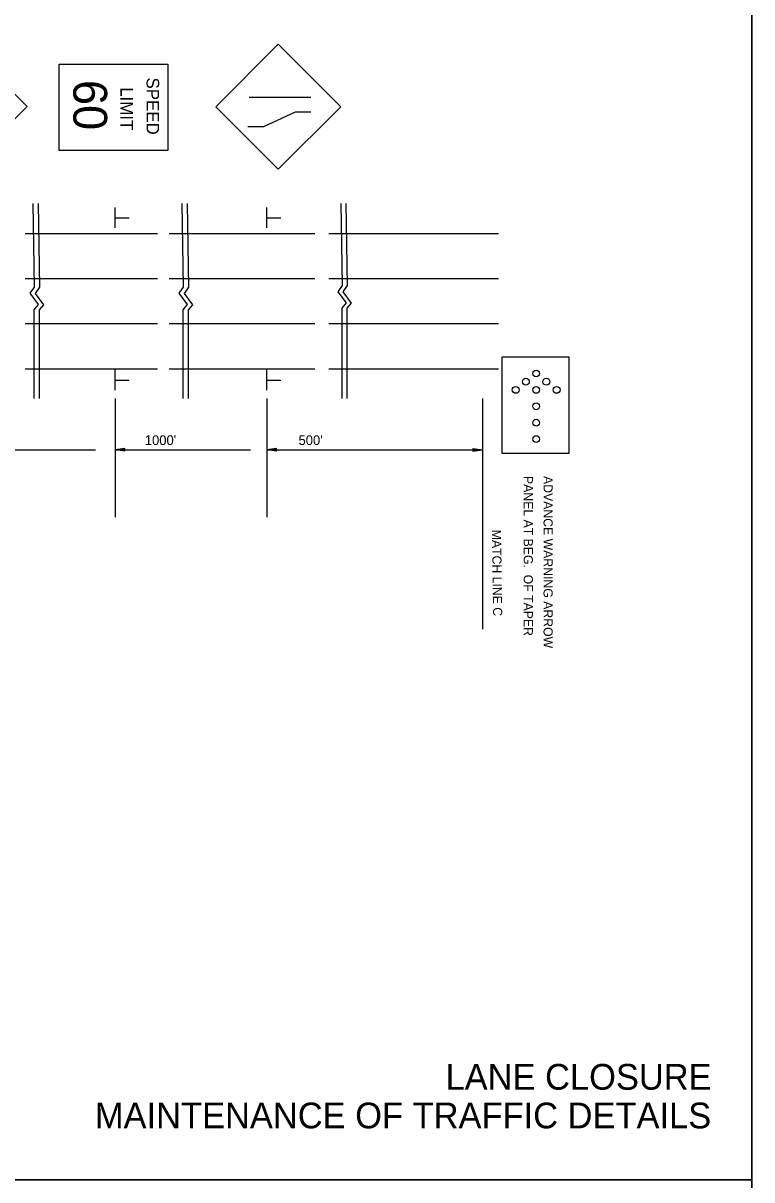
# Model space of a CAD drawing. Extents: x -100 to 745, y -1581 to -107.
# Drawn here: x 295.9 to 345.4, y -810.6 to -732 of the extents above; entities that cross this region are included whole.
import ezdxf

# ---------------------------------------------------------------- set-up
doc = ezdxf.new("R2010")
doc.units = 0
for name, color, linetype in [('Default', 7, 'Continuous'), ('R_Contour Annot', 7, 'Continuous'), ('R_Draft', 7, 'Continuous'), ('R_MOT', 7, 'Continuous')]:
    doc.layers.add(name, color=color, linetype=linetype)

msp = doc.modelspace()

# ---------------------------------------------------------------- linework, layer by layer
at = {"layer": 'Default'}
for p, q in [((291.935, -733.443), (296.177, -737.674)), ((308.988, -737.689), (313.233, -733.444)), ((313.233, -733.444), (317.477, -737.689)), ((311.266, -737.041), (315.442, -737.041)), ((296.177, -737.674), (291.95, -741.919)), ((313.233, -741.933), (308.988, -737.689)), ((317.477, -737.689), (313.233, -741.933)), ((312.257, -739.02), (314.414, -738.03)), ((314.414, -738.03), (315.442, -738.03)), ((311.176, -739.02), (312.257, -739.02)), ((302.151, -745.916), (302.151, -744.538)), ((312.458, -745.916), (312.458, -744.538)), ((302.171, -745.231), (303.112, -745.231)), ((312.478, -745.231), (313.419, -745.231)), ((296.044, -746.294), (305.039, -746.294)), ((305.818, -746.294), (315.713, -746.294)), ((316.663, -746.294), (324.214, -746.294)), ((324.214, -746.294), (328.2, -746.294)), ((296.044, -749.356), (305.039, -749.356)), ((305.818, -749.356), (315.713, -749.356)), ((316.663, -749.356), (324.214, -749.356)), ((324.214, -749.356), (328.2, -749.356)), ((296.044, -752.419), (305.039, -752.419)), ((305.818, -752.419), (315.713, -752.419)), ((316.663, -752.419), (324.214, -752.419)), ((324.214, -752.419), (328.2, -752.419)), ((296.044, -755.481), (305.039, -755.481)), ((302.151, -756.938), (302.151, -755.56)), ((305.818, -755.481), (315.713, -755.481)), ((312.458, -756.938), (312.458, -755.56)), ((316.663, -755.481), (324.214, -755.481)), ((324.214, -755.481), (328.2, -755.481)), ((302.171, -756.252), (303.112, -756.252)), ((312.479, -756.252), (313.419, -756.252)), ((302.151, -757.508), (302.151, -765.561)), ((312.458, -757.508), (312.458, -765.561)), ((327.11, -757.508), (327.11, -773.174)), ((291.636, -760.99), (300.829, -760.99)), ((302.812, -760.891), (302.151, -760.99)), ((302.151, -760.99), (311.344, -760.99)), ((302.812, -761.089), (302.151, -760.99)), ((302.812, -760.907), (302.261, -760.99)), ((302.812, -761.072), (302.261, -760.99)), ((302.812, -760.924), (302.375, -760.99)), ((302.812, -761.056), (302.375, -760.99)), ((302.812, -760.941), (302.485, -760.99)), ((302.812, -761.039), (302.485, -760.99)), ((302.812, -760.957), (302.597, -760.99)), ((302.812, -761.022), (302.597, -760.99)), ((302.812, -760.974), (302.707, -760.99)), ((302.812, -761.005), (302.707, -760.99)), ((302.812, -761.089), (302.812, -760.891)), ((313.119, -760.891), (312.458, -760.99)), ((313.119, -761.089), (312.458, -760.99)), ((312.458, -760.99), (327.11, -760.99)), ((313.119, -760.907), (312.569, -760.99)), ((313.119, -761.072), (312.569, -760.99)), ((313.119, -760.924), (312.682, -760.99)), ((313.119, -761.056), (312.682, -760.99)), ((313.119, -760.941), (312.792, -760.99)), ((313.119, -761.039), (312.792, -760.99)), ((313.119, -760.957), (312.904, -760.99)), ((313.119, -761.022), (312.904, -760.99)), ((313.119, -760.974), (313.014, -760.99)), ((313.119, -761.005), (313.014, -760.99)), ((313.119, -761.089), (313.119, -760.891)), ((326.449, -760.891), (327.11, -760.99)), ((326.449, -760.891), (326.449, -761.089)), ((326.449, -760.907), (327, -760.99)), ((326.449, -760.924), (326.886, -760.99)), ((326.449, -760.941), (326.776, -760.99)), ((326.449, -760.958), (326.664, -760.99)), ((326.449, -760.974), (326.554, -760.99)), ((326.449, -761.089), (327.11, -760.99)), ((326.449, -761.022), (326.664, -760.99)), ((326.449, -761.056), (326.886, -760.99)), ((326.449, -761.072), (327, -760.99)), ((326.449, -761.039), (326.776, -760.99)), ((326.449, -761.005), (326.554, -760.99))]:
    msp.add_line(p, q, dxfattribs=at)
for points in [[(305.726, -740.647), (298.359, -740.647), (298.359, -734.802), (305.726, -734.802)], [(328.434, -761.243), (328.434, -754.683), (332.972, -754.683), (332.972, -761.243)]]:
    msp.add_lwpolyline(points, close=True, dxfattribs=at)
for points in [[(296.57, -744.267), (296.657, -749.931), (296.371, -750.357), (296.928, -751.119), (296.635, -751.472), (296.633, -757.508)], [(296.922, -744.267), (297.008, -749.946), (296.722, -750.371), (297.28, -751.134), (296.986, -751.486), (296.985, -757.508)], [(306.692, -744.267), (306.778, -749.931), (306.492, -750.357), (307.05, -751.119), (306.756, -751.472), (306.755, -757.508)], [(307.044, -744.267), (307.13, -749.946), (306.844, -750.371), (307.402, -751.134), (307.108, -751.486), (307.107, -757.508)], [(317.483, -744.267), (317.567, -749.82), (317.281, -750.246), (317.839, -751.008), (317.545, -751.36), (317.544, -757.508)], [(317.835, -744.267), (317.919, -749.835), (317.633, -750.26), (318.19, -751.023), (317.897, -751.375), (317.896, -757.508)]]:
    msp.add_lwpolyline(points, dxfattribs=at)
for centre in [(330.754, -755.804), (329.364, -756.918), (330.059, -756.361), (330.754, -756.918), (331.449, -756.361), (332.144, -756.918), (330.754, -758.032), (330.754, -759.146), (330.754, -760.26)]:
    msp.add_circle(centre, 0.231, dxfattribs=at)
at = {"layer": 'R_Contour Annot'}
for points in [[(175.406, -700.582), (345.406, -700.582), (345.406, -810.582), (175.406, -810.582)], [(175.406, -810.582), (345.406, -810.582), (345.406, -920.582), (175.406, -920.582)]]:
    msp.add_lwpolyline(points, close=True, dxfattribs=at)
at = {"layer": 'R_Draft'}
for points in [[(175.406, -700.582), (175.406, -810.582), (345.406, -810.582), (345.406, -700.582)], [(175.406, -810.582), (175.406, -920.582), (345.406, -920.582), (345.406, -810.582)]]:
    msp.add_lwpolyline(points, close=True, dxfattribs=at)

# ---------------------------------------------------------------- texts
at = {"layer": 'Default'}
for s, height, rotation, p in [('60', 2.2968, 270, (299.316, -735.86)), ('SPEED', 0.857, 270, (304.289, -735.701)), ('LIMIT', 0.857, 270, (302.518, -736.358)), ('PANEL AT BEG.  OF TAPER', 0.6222, 270, (329.908, -762.768)), ('ADVANCE WARNING ARROW', 0.6222, 270, (331.254, -762.768)), ('MATCH LINE C', 0.6222, 270.80593, (327.747, -766.42))]:
    msp.add_text(s, height=height, rotation=rotation, dxfattribs=at).set_placement(p)
for s, p in [("1000'", (304.17, -760.664)), ("500'", (314.612, -760.664))]:
    msp.add_text(s, height=0.6606, dxfattribs=at).set_placement(p)
at = {"layer": 'R_MOT'}
for s, p in [('LANE CLOSURE', (324.596, -804.457)), ('MAINTENANCE OF TRAFFIC DETAILS', (300.779, -807.082))]:
    msp.add_text(s, height=1.75, dxfattribs=at).set_placement(p)

doc.saveas('drawing.dxf')
